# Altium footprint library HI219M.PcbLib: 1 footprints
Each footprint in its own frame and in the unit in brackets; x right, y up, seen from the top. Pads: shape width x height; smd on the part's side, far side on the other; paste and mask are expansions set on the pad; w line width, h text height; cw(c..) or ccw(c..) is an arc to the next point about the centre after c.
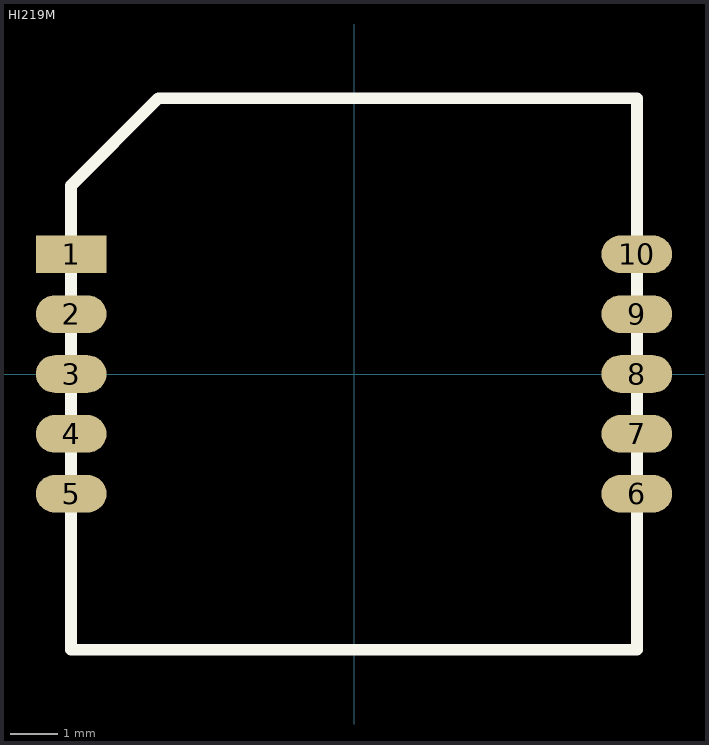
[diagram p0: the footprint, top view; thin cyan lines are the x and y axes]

## HI219M [mm]
pads (10):
  rect 1.5x0.8 smd: 1(-6,2.54)
  oval 1.5x0.8 smd: 2(-6,1.27) 3(-6,0) 4(-6,-1.27) 5(-6,-2.54) 6(6,-2.54) 7(6,-1.27) 8(6,0) 9(6,1.27) 10(6,2.54)
Top Overlay:
  lines w0.254: -6,-5.85 -6,4 -4.15,5.85 -4,5.85 6,5.85 6,-5.85 -6,-5.85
